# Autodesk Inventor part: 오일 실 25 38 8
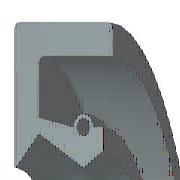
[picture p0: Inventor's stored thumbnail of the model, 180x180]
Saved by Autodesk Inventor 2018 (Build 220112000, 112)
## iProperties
Created: 2012-02
Part Number: 오일 실 25 38 8
Material: 고무
Description: 오일-실
Document SubType Name: Modeling
Standard: KS B 2804
Designer: mduedu
Standards Organization: KS
Language: ko-KR
Size Designation: D - 25 38 8
Categories: <MemberInstance><Categories><Category DisplayName="샤프트 부품" InternalName="7f7aeb1f-a693-4053-b835-cee3144e0d98" Mnemonic="SHFT"><Category DisplayName="실링" Intern
Density: 0.93 g/cm^3
Appearance: 고무 - 검은색 - 버전 1.1
IsCustomPart: 1
Author: mduedu
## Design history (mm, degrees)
revolve "본체" stored, may be unused: angle "d17" = 90 deg
revolve "스프링1" stored, may be unused: angle "d18" = 90 deg
body "Solid1"
sketch "스케치1"
  geometry: L1 (0, 19)-(8, 19); L2 (8, 17.25)-(1.75, 17.25); L3 (1.75, 14.25)-(4.9, 12.5); L4 (4.9, 12.5)-(0, 12.5); L5 (0, 0)-(9.586, 0) reference; L6 (4.9, 12.5)-(6.3, 13.375); L7 (0, 18)-(0, -3) reference; L8 (-1.941, 0)-(11.507, 0) reference; L9 (4.2, 14.6)-(1.75, 15.21); L10 (1.75, 15.21)-(1.75, 17.25); L11 (0, 19)-(0, 12.588); L12 (4.9, 12.5)-(0, 12.5); L13 (1.75, 14.25)-(0.152, 12.528); L14 (8, 19)-(8, 17.25); L15 (5.6, 14.6)-(6.3, 14.6); L16 (6.3, 14.6)-(6.3, 13.375); C1 r 0.455 at (4.9, 14.6); A1 r 0.7 centre (4.9, 14.6) between (5.6, 14.6) and (4.2, 14.6); A2 r 0.088 centre (0.087, 12.588) between (0, 12.588) and (0.152, 12.528); 1 further point
  constraints: 28 end point, 5 horizontal alignment, 5 point on line, 4 point on circle, 4 vertical alignment, 3 centre point, 3 tangent, 2 collinear, 2 horizontal, 2 perpendicular, 1 coincident, 1 parallel
  dimensions: "d0" = 38 diameter of L1 L5 (= SD2); "d1" = 1.75 distance of L1.end L2.start (= SD); "d2" = 0.91 diameter of C1 (= SPDI); "d3" = 1.4 diameter of A1 (= SPDA); "d4" = 25 diameter of L3.end L5 (= NND); "d5" = 28.5 diameter of L3.start L5 (= TKDM); "d7" = 30.42 diameter of L9.end L5 (= TKDM + 0.24 x SWDT); "d8" = 1.75 distance between parallel lines of L11 L10 (= SD); "d9" = 4.9 distance from line of L11 C1.centre (= SPDST); "d10" = 29.2 diameter of C1.centre L5 (= HLDM); "d11" = 0.0875 radius of A2 (= 0.25 x LAB); "d12" = 6.3 distance between parallel lines of L11 L16 (= SDI); "d13" = 26.75 diameter of L6.end L5 (= ABDM); "d14" = 8 distance from line of L11 L1.end (= SWDT)
fillet "모깎기1" dims "d6" = 0.3 (= RR)
other parameters: "SD2" = 38 [user parameter; used in 1 equation term], "SWDT" = 8 [user parameter; used in 2 equation terms], "RR" = 0.3 [user parameter; used in 1 equation term], "SD" = 1.75 [user parameter; used in 2 equation terms], "NND" = 25 [user parameter; used in 1 equation term], "SPDA" = 1.4 [user parameter; used in 1 equation term], "SPDI" = 0.91 [user parameter; used in 1 equation term], "TKDM" = 28.5 [user parameter; used in 2 equation terms], "HLDM" = 29.2 [user parameter; used in 1 equation term], "ABDM" = 26.75 [user parameter; used in 1 equation term], "SDI" = 6.3 [user parameter; used in 1 equation term], "SPDST" = 4.9 [user parameter; used in 1 equation term], "LAB" = 0.35 [user parameter; used in 1 equation term], "d15" = 0, "d16" = 0, "d19" = 0
